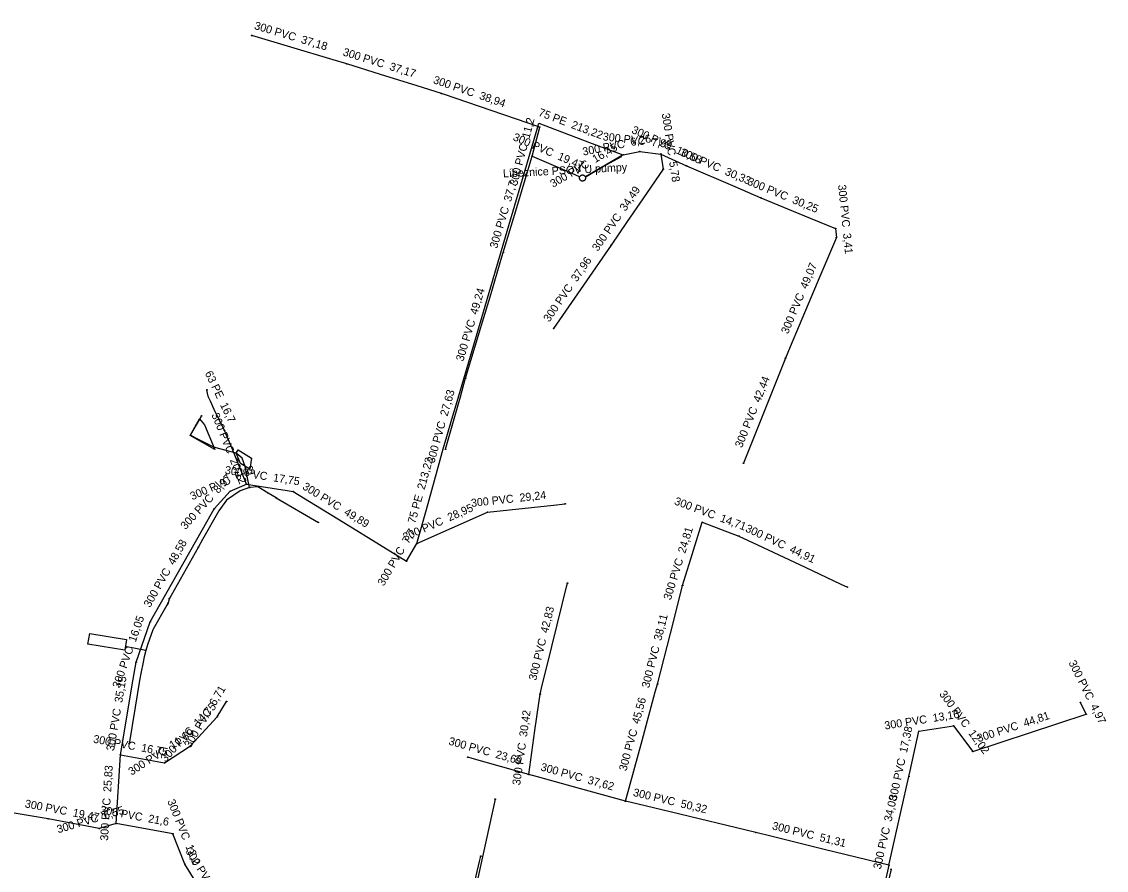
# Model space of a CAD drawing. Extents: x -736536 to -735428, y -1032997 to -1031649.
# Drawn here: x -736011.6 to -735605.1, y -1031966.8 to -1031648.8 of the extents above; entities that cross this region are included whole.
import ezdxf

# ---------------------------------------------------------------- set-up
doc = ezdxf.new("R2010")
doc.units = 0
for name, color, linetype in [('Vrstva 1', 7, 'Continuous'), ('Vrstva 20', 7, 'Continuous'), ('Vrstva 26', 7, 'Continuous'), ('Vrstva 29', 7, 'Continuous'), ('Vrstva 31', 7, 'Continuous'), ('Vrstva 63', 7, 'Continuous')]:
    doc.layers.add(name, color=color, linetype=linetype)

# ---------------------------------------------------------------- blocks, each defined once
blk = doc.blocks.new('100')
at = {"layer": 'Vrstva 1'}
blk.add_circle((0, 0), 0.127, dxfattribs=at)

msp = doc.modelspace()

# ---------------------------------------------------------------- linework, layer by layer
at = {"layer": 'Vrstva 20'}
for p, q in [((-735820.296, -1031699.16), (-735817.455, -1031688.322)), ((-735786.106, -1031698.693), (-735779.97, -1031697.473)), ((-735779.97, -1031697.473), (-735772.029, -1031698.389)), ((-735786.106, -1031698.693), (-735800.311, -1031706.996)), ((-735772.029, -1031698.389), (-735771.155, -1031704.099)), ((-735772.029, -1031698.389), (-735762.411, -1031702.801)), ((-735706.576, -1031726.287), (-735706.228, -1031729.678)), ((-735934.93, -1031803.47), (-735935.609, -1031802.05)), ((-735933.449, -1031824.778), (-735927.373, -1031822.12)), ((-735939.48, -1031831.417), (-735933.449, -1031824.778)), ((-735916.227, -1031827.217), (-735919.28, -1031825.43)), ((-735916.227, -1031827.217), (-735900.419, -1031836.451)), ((-735863.443, -1031844.339), (-735836.971, -1031832.623)), ((-735756.516, -1031836.412), (-735742.743, -1031841.571)), ((-735867.326, -1031850.993), (-735863.443, -1031844.339)), ((-735968.698, -1031888.847), (-735963.427, -1031873.69)), ((-735965.149, -1031884.46), (-735972.819, -1031882.989)), ((-735938.3, -1031909.34), (-735934.869, -1031903.569)), ((-735612.55, -1031908.34), (-735614.77, -1031903.89)), ((-735655.13, -1031922.3), (-735612.55, -1031908.34)), ((-735948.31, -1031920.17), (-735938.3, -1031909.34)), ((-735675.286, -1031914.711), (-735662.29, -1031912.64)), ((-735662.29, -1031912.64), (-735655.13, -1031922.3)), ((-735958.13, -1031926.52), (-735948.31, -1031920.17)), ((-735976.239, -1031949.279), (-735974.609, -1031923.5)), ((-735974.609, -1031923.5), (-735958.13, -1031926.52)), ((-735834.138, -1031940.181), (-735843.846, -1031984.129)), ((-735982.52, -1031951.151), (-736001.655, -1031947.538)), ((-735976.239, -1031949.279), (-735982.52, -1031951.151)), ((-735954.989, -1031953.149), (-735976.239, -1031949.279)), ((-735950.439, -1031964.47), (-735954.989, -1031953.149)), ((-735686.54, -1031964.89), (-735693.87, -1031996.69)), ((-735685.74, -1031966.45), (-735693.01, -1031998.06))]:
    msp.add_line(p, q, dxfattribs=at)
for points in [[(-735889.783, -1031664.645), (-735894.91, -1031663.114), (-735910.794, -1031658.372), (-735925.414, -1031654.008)], [(-735854.293, -1031675.69), (-735863.352, -1031672.875), (-735877.153, -1031668.578), (-735889.783, -1031664.645)], [(-735817.455, -1031688.322), (-735853.553, -1031675.944), (-735854.293, -1031675.69)], [(-735863.443, -1031844.339), (-735859.904, -1031831.549), (-735857.921, -1031824.379), (-735855.923, -1031817.158), (-735853.638, -1031808.899), (-735852.278, -1031804.273), (-735850.361, -1031797.75), (-735848.411, -1031791.117), (-735845.313, -1031780.577), (-735841.563, -1031767.821), (-735838.542, -1031757.541), (-735833.652, -1031740.908), (-735829.042, -1031725.225), (-735822.326, -1031702.377), (-735818.543, -1031689.506), (-735817.775, -1031686.893), (-735809.294, -1031690.074), (-735797.784, -1031694.392), (-735786.849, -1031698.493), (-735786.818, -1031698.949), (-735787.205, -1031699.516), (-735792.386, -1031702.509), (-735798.171, -1031705.852), (-735799.174, -1031706.431), (-735800.286, -1031707.074)], [(-735831.109, -1031735.277), (-735826.452, -1031719.721), (-735822.564, -1031706.734), (-735820.296, -1031699.16)], [(-735820.296, -1031699.16), (-735805.44, -1031705.571), (-735802.689, -1031706.759), (-735802.422, -1031706.874)], [(-735771.155, -1031704.099), (-735778.751, -1031715.131), (-735784.659, -1031723.711), (-735790.716, -1031732.506)], [(-735762.411, -1031702.801), (-735744.254, -1031710.598), (-735734.544, -1031714.767)], [(-735734.544, -1031714.767), (-735716.049, -1031722.385), (-735706.576, -1031726.287)], [(-735706.228, -1031729.678), (-735712.382, -1031744.269), (-735720.139, -1031762.658), (-735723.519, -1031770.672), (-735725.298, -1031774.89)], [(-735790.716, -1031732.506), (-735801.077, -1031747.573), (-735812.226, -1031763.786)], [(-735845.23, -1031782.445), (-735841.615, -1031770.369), (-735839.644, -1031763.785), (-735838.901, -1031761.304), (-735836.076, -1031751.867), (-735831.602, -1031736.925), (-735831.109, -1031735.277)], [(-735725.298, -1031774.89), (-735731.533, -1031790.462), (-735738.308, -1031807.383), (-735741.072, -1031814.286)], [(-735852.743, -1031809.036), (-735850.503, -1031801.107), (-735847.794, -1031791.518), (-735847.178, -1031789.338), (-735845.838, -1031784.595), (-735845.23, -1031782.445)], [(-735935.609, -1031802.05), (-735939.418, -1031794.096), (-735940.889, -1031791.024), (-735941.59, -1031789.56), (-735941.735, -1031789.104), (-735941.88, -1031788.649), (-735942.18, -1031786.779)], [(-735948.319, -1031803.8), (-735946.419, -1031800.452), (-735944.519, -1031797.105), (-735944.206, -1031796.553)], [(-735927.373, -1031822.12), (-735932.78, -1031808.776), (-735934.93, -1031803.47)], [(-735931.25, -1031810.5), (-735937.355, -1031808.818), (-735939.56, -1031808.21), (-735946.29, -1031804.821), (-735948.319, -1031803.8)], [(-735926.22, -1031823.35), (-735927.844, -1031815.494), (-735928.962, -1031812.392), (-735931.25, -1031810.5)], [(-735926.22, -1031823.35), (-735929.737, -1031824.613), (-735934.79, -1031828.132), (-735937.7, -1031832.116), (-735943.799, -1031842.904), (-735945.431, -1031845.791)], [(-735927.373, -1031822.12), (-735912.103, -1031824.51), (-735909.832, -1031824.865)], [(-735919.28, -1031825.43), (-735923.13, -1031823.09), (-735926.22, -1031823.35)], [(-735909.832, -1031824.865), (-735890.865, -1031836.53), (-735877.547, -1031844.725), (-735867.326, -1031850.993)], [(-735963.427, -1031873.69), (-735957.582, -1031863.372), (-735948.545, -1031847.419), (-735943.842, -1031839.116), (-735939.48, -1031831.417)], [(-735836.971, -1031832.623), (-735812.224, -1031829.935), (-735807.903, -1031829.466)], [(-735763.911, -1031860.098), (-735760.263, -1031848.513), (-735756.516, -1031836.412)], [(-735742.743, -1031841.571), (-735735.83, -1031844.844), (-735717.973, -1031853.263), (-735704.55, -1031859.595), (-735702.107, -1031860.686)], [(-735945.431, -1031845.791), (-735955.633, -1031863.856), (-735956.263, -1031864.971)], [(-735817.282, -1031900.798), (-735816.768, -1031898.592), (-735812.907, -1031882.975), (-735808.872, -1031866.657), (-735807.243, -1031860.067), (-735807.018, -1031859.213)], [(-735773.296, -1031897.029), (-735767.226, -1031873.214), (-735763.911, -1031860.098)], [(-735956.757, -1031866.687), (-735957.155, -1031867.424), (-735962.381, -1031876.493), (-735962.507, -1031876.718), (-735964.427, -1031882.346), (-735965.149, -1031884.46)], [(-735956.263, -1031864.971), (-735956.373, -1031865.176), (-735956.699, -1031866.579), (-735956.757, -1031866.687)], [(-735965.149, -1031884.46), (-735965.726, -1031886.865), (-735966.275, -1031889.424), (-735966.896, -1031892.397), (-735967.435, -1031895.655), (-735969.1, -1031905.714), (-735971.359, -1031919.369)], [(-735974.609, -1031923.5), (-735969.79, -1031895.246), (-735968.698, -1031888.847)], [(-735821.573, -1031930.911), (-735819.243, -1031914.411), (-735817.792, -1031904.169), (-735817.282, -1031900.798)], [(-735785.319, -1031940.973), (-735779.082, -1031918.17), (-735774.11, -1031899.924), (-735773.296, -1031897.029)], [(-735679.027, -1031931.646), (-735678.558, -1031929.492), (-735675.34, -1031914.72), (-735675.286, -1031914.711)], [(-735821.573, -1031930.911), (-735842.776, -1031924.92), (-735844.365, -1031924.466)], [(-735785.319, -1031940.973), (-735802.472, -1031936.196), (-735818.252, -1031931.832), (-735821.573, -1031930.911)], [(-735686.54, -1031964.89), (-735686.184, -1031963.313), (-735681.905, -1031944.382), (-735679.03, -1031931.66), (-735679.027, -1031931.646)], [(-736001.655, -1031947.538), (-736020.574, -1031944.355), (-736026.457, -1031943.366), (-736039.331, -1031941.2), (-736047.575, -1031939.813)], [(-735736.376, -1031952.663), (-735768.585, -1031944.958), (-735780.541, -1031942.091), (-735785.319, -1031940.973)], [(-735686.54, -1031964.89), (-735710.762, -1031958.968), (-735730.309, -1031954.179), (-735736.376, -1031952.663)], [(-735851.498, -1032013.031), (-735848.58, -1032000.434), (-735846.456, -1031991.334), (-735844.114, -1031981.299), (-735839.958, -1031963.488), (-735839.492, -1031961.535)], [(-735932.31, -1031993.89), (-735944.301, -1031974.43), (-735950.439, -1031964.47)]]:
    msp.add_lwpolyline(points, dxfattribs=at)
at = {"layer": 'Vrstva 26'}
msp.add_lwpolyline([(-735802.492, -1031707.702), (-735802.515, -1031707.619), (-735802.53, -1031707.522), (-735802.538, -1031707.41), (-735802.533, -1031707.26), (-735802.508, -1031707.141), (-735802.484, -1031707.026), (-735802.422, -1031706.874), (-735802.386, -1031706.807), (-735802.321, -1031706.706), (-735802.263, -1031706.635), (-735802.16, -1031706.528), (-735802.067, -1031706.452), (-735801.912, -1031706.359), (-735801.776, -1031706.3), (-735801.689, -1031706.274), (-735801.596, -1031706.253), (-735801.512, -1031706.239), (-735801.459, -1031706.236), (-735801.392, -1031706.233), (-735801.288, -1031706.238), (-735801.213, -1031706.249), (-735801.154, -1031706.258), (-735801.096, -1031706.274), (-735801.038, -1031706.289), (-735800.926, -1031706.332), (-735800.819, -1031706.387), (-735800.741, -1031706.437), (-735800.671, -1031706.49), (-735800.604, -1031706.548), (-735800.486, -1031706.679), (-735800.417, -1031706.779), (-735800.358, -1031706.887), (-735800.326, -1031706.959), (-735800.286, -1031707.074), (-735800.25, -1031707.282), (-735800.245, -1031707.38), (-735800.251, -1031707.5), (-735800.261, -1031707.56), (-735800.301, -1031707.735), (-735800.358, -1031707.874), (-735800.396, -1031707.949), (-735800.464, -1031708.055), (-735800.558, -1031708.166), (-735800.671, -1031708.271), (-735800.786, -1031708.353), (-735800.872, -1031708.401), (-735800.93, -1031708.43), (-735801.038, -1031708.472), (-735801.154, -1031708.503), (-735801.272, -1031708.522), (-735801.363, -1031708.526), (-735801.502, -1031708.522), (-735801.596, -1031708.508), (-735801.747, -1031708.472), (-735801.843, -1031708.435), (-735801.97, -1031708.371), (-735802.081, -1031708.297), (-735802.16, -1031708.233), (-735802.21, -1031708.184), (-735802.251, -1031708.14), (-735802.313, -1031708.064), (-735802.364, -1031707.988), (-735802.408, -1031707.911), (-735802.44, -1031707.847), (-735802.457, -1031707.804), (-735802.466, -1031707.781), (-735802.478, -1031707.749), (-735802.492, -1031707.702)], dxfattribs=at)
at = {"layer": 'Vrstva 31'}
for points in [[(-735939.182, -1031809.087), (-735948.514, -1031803.821), (-735944.921, -1031797.648), (-735943.1, -1031799.849), (-735939.182, -1031809.087)], [(-735930.517, -1031809.294), (-735925.423, -1031812.399), (-735926.105, -1031816.554), (-735929.583, -1031814.435), (-735931.25, -1031810.5), (-735930.517, -1031809.294)], [(-735986.123, -1031878.072), (-735972.316, -1031880.387), (-735972.977, -1031884.332), (-735986.785, -1031882.017), (-735986.123, -1031878.072)]]:
    msp.add_lwpolyline(points, dxfattribs=at)

# ---------------------------------------------------------------- block references
at = {"layer": 'Vrstva 29'}
for p, xscale, yscale, rotation in [((-735925.414, -1031654.008), 1.035124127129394, 1.0351241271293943, 157.49634583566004), ((-735889.783, -1031664.645), 1.0335064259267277, 1.033506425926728, -23.04128150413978), ((-735854.293, -1031675.69), 1.0316957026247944, 1.0316957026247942, -23.584588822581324), ((-735817.455, -1031688.322), 0.9999999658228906, 0.9999999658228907, 117.99999982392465), ((-735779.97, -1031697.473), 0.9999999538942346, 0.9999999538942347, 2.0000000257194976), ((-735820.296, -1031699.16), 1.0169561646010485, 1.0169561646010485, 26.97601647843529), ((-735786.106, -1031698.693), 1.0275072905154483, 1.027507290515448, 24.689105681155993), ((-735772.029, -1031698.389), 1.035124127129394, 1.0351241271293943, -22.503654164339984), ((-735771.155, -1031704.099), 0.9999999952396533, 0.9999999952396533, 77.00000056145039), ((-735762.411, -1031702.801), 1.0169561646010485, 1.0169561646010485, -26.97601647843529), ((-735734.544, -1031714.767), 1.0198568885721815, 1.0198568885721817, -26.39398240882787), ((-735706.576, -1031726.287), 0.9999999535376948, 0.9999999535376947, -53.99999865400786), ((-735706.228, -1031729.678), 0.9999999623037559, 0.999999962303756, 80.99999986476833), ((-735790.716, -1031732.506), 0.9999999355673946, 0.9999999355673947, 55.0000006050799), ((-735831.109, -1031735.277), 0.9999999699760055, 0.9999999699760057, 73.00000033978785), ((-735812.226, -1031763.786), 0.9999999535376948, 0.9999999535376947, -126.00000134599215), ((-735725.298, -1031774.89), 0.9999999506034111, 0.9999999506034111, 67.99999971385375), ((-735845.23, -1031782.445), 0.9999999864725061, 0.9999999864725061, 74.0000013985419), ((-735942.18, -1031786.779), 0.9999999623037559, 0.999999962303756, 99.00000013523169), ((-735944.206, -1031796.553), 0.9999999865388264, 0.9999999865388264, 59.99999955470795), ((-735935.609, -1031802.05), 0.9999999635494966, 0.9999999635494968, -65.00000039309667), ((-735934.93, -1031803.47), 0.9999999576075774, 0.9999999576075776, -66.99999911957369), ((-735948.319, -1031803.8), 0.9999999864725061, 0.9999999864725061, -74.0000013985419), ((-735931.25, -1031810.5), 1.0072562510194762, 1.0072562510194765, -28.766663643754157), ((-735852.743, -1031809.036), 0.9999999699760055, 0.9999999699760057, -106.99999966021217), ((-735741.072, -1031814.286), 0.9999999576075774, 0.9999999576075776, -113.00000088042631), ((-735927.373, -1031822.12), 0.9999999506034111, 0.9999999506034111, 67.99999971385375), ((-735926.22, -1031823.35), 1.0045862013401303, 1.00458620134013, 13.17409066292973), ((-735933.449, -1031824.778), 0.9999999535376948, 0.9999999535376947, 36.000001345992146), ((-735919.28, -1031825.43), 0.9999999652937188, 0.9999999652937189, -31.9999973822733), ((-735916.227, -1031827.217), 0.9999999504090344, 0.9999999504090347, -31.000001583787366), ((-735909.832, -1031824.865), 1.0275072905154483, 1.027507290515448, -24.689105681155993), ((-735939.48, -1031831.417), 0.9999999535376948, 0.9999999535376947, 53.99999865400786), ((-735807.903, -1031829.466), 1.0011216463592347, 1.0011216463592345, 6.5826102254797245), ((-735836.971, -1031832.623), 0.999999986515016, 0.9999999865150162, 15.000000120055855), ((-735900.419, -1031836.451), 0.9999999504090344, 0.9999999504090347, -31.000001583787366), ((-735756.516, -1031836.412), 1.0138864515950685, 1.0138864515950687, 27.5653151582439), ((-735742.743, -1031841.571), 1.0198568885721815, 1.0198568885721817, -26.39398240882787), ((-735945.431, -1031845.791), 0.999999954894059, 0.9999999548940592, 60.999999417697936), ((-735863.443, -1031844.339), 0.9999999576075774, 0.9999999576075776, 66.99999911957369), ((-735867.326, -1031850.993), 1.0028916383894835, 1.0028916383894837, -166.30279209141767), ((-735807.018, -1031859.213), 0.999999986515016, 0.9999999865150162, 74.99999987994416), ((-735763.911, -1031860.098), 0.9999999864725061, 0.9999999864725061, 74.0000013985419), ((-735702.107, -1031860.686), 1.0169561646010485, 1.0169561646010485, -26.97601647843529), ((-735956.263, -1031864.971), 0.999999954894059, 0.9999999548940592, 60.999999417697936), ((-735963.427, -1031873.69), 0.9999999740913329, 0.9999999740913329, 65.99999939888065), ((-735965.149, -1031884.46), 0.9999999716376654, 0.9999999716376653, 29.999998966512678), ((-735968.698, -1031888.847), 0.9999999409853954, 0.9999999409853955, 75.99999967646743), ((-735773.296, -1031897.029), 0.999999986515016, 0.9999999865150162, 74.99999987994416), ((-735817.282, -1031900.798), 0.9999999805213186, 0.9999999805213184, 79.00000058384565), ((-735934.869, -1031903.569), 0.9999999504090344, 0.9999999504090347, 58.99999841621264), ((-735614.77, -1031903.89), 0.999999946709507, 0.999999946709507, 117.00000088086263), ((-735938.3, -1031909.34), 0.9999999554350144, 0.9999999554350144, 53.00000079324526), ((-735612.55, -1031908.34), 0.9999999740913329, 0.9999999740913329, -114.00000060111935), ((-735662.29, -1031912.64), 1.025136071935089, 1.0251360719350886, 154.74924162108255), ((-735675.286, -1031914.711), 1.00837761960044, 1.00837761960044, 11.626378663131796), ((-735971.359, -1031919.369), 0.9999999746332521, 0.9999999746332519, -99.99999944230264), ((-735948.31, -1031920.17), 0.9999999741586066, 0.9999999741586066, 39.999998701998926), ((-735974.609, -1031923.5), 1.000191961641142, 1.000191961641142, 82.91099886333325), ((-735844.365, -1031924.466), 1.0365458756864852, 1.0365458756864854, 158.02850914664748), ((-735655.13, -1031922.3), 1.0335064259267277, 1.033506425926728, 156.95871849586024), ((-735958.13, -1031926.52), 1.0060666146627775, 1.0060666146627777, 12.654735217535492), ((-735821.573, -1031930.911), 1.035124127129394, 1.0351241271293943, -22.503654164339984), ((-735679.027, -1031931.646), 0.999999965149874, 0.9999999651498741, 77.9999999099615), ((-735834.138, -1031940.181), 0.9999999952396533, 0.9999999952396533, -102.9999994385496), ((-735785.319, -1031940.973), 0.999999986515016, 0.9999999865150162, -15.000000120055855), ((-736001.655, -1031947.538), 1.0060666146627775, 1.0060666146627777, -12.654735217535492), ((-735976.239, -1031949.279), 1.0002788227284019, 1.0002788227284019, 3.2906995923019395), ((-735982.52, -1031951.151), 1.0002788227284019, 1.0002788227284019, 3.2906995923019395), ((-735954.989, -1031953.149), 0.9999999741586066, 0.9999999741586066, -39.999998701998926), ((-735736.376, -1031952.663), 0.999999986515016, 0.9999999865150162, -15.000000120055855), ((-735839.492, -1031961.535), 0.9999999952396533, 0.9999999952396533, 77.00000056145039), ((-735950.439, -1031964.47), 0.9999999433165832, 0.999999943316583, -64.0000000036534), ((-735686.54, -1031964.89), 0.9999999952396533, 0.9999999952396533, 77.00000056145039), ((-735685.74, -1031966.45), 0.9999999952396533, 0.9999999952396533, 77.00000056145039)]:
    msp.add_blockref('100', p, dxfattribs=dict(at, xscale=xscale, yscale=yscale, rotation=rotation))
msp.add_blockref('100', (-735956.757, -1031866.687), dxfattribs=at)

# ---------------------------------------------------------------- texts
at = {"layer": 'Vrstva 63'}
for s, rotation, p in [('300 PVC  37,18', 343.38, (-735924.664, -1031651.519)), ('300 PVC  37,17', 342.7, (-735891.467, -1031661.395)), ('300 PVC  38,94', 341.07, (-735857.628, -1031671.797)), ('75 PE  213,22', 339.44, (-735818.199, -1031683.956)), ('300 PVC  11,2', 75.31, (-735825.947, -1031710.464)), ('300 PVC  5,78', 278.7, (-735771.707, -1031683.302)), ('300 PVC  10,58', 335.36, (-735783.267, -1031690.373)), ('300 PVC  19,47', 336.66, (-735827.753, -1031693.111)), ('300 PVC  6,26', 11.25, (-735801.098, -1031699.024)), ('300 PVC  7,99', 353.42, (-735793.918, -1031693.246)), ('300 PVC  16,45', 30.31, (-735812.42, -1031711.063)), ('300 PVC  30,33', 336.76, (-735765.099, -1031698.816)), ('Líbeznice PSOV U pumpy', 3, (-735831.149, -1031707.191)), ('300 PVC  37,7', 73.33, (-735833.442, -1031734)), ('300 PVC  30,25', 337.61, (-735739.905, -1031709.746)), ('300 PVC  3,41', 275.86, (-735705.633, -1031710.002)), ('300 PVC  34,49', 55.45, (-735795.655, -1031735.095)), ('300 PVC  37,96', 55.49, (-735813.872, -1031761.594)), ('300 PVC  49,07', 67.13, (-735724.392, -1031766.053)), ('300 PVC  49,24', 73.33, (-735846.106, -1031776.302)), ('63 PE  16,7', 295.59, (-735943.045, -1031780.5)), ('300 PVC  42,44', 68.18, (-735741.646, -1031808.728)), ('300 PVC  27,63', 74.22, (-735856.975, -1031814.448)), ('300 PVC  20,12', 292.06, (-735940.545, -1031796.119)), ('300 PVC  6,63', 23.63, (-735947.708, -1031828.178)), ('300 PVC  17,75', 351.11, (-735935.61, -1031818.2)), ('75 PE  213,22', 74.54, (-735864.126, -1031837.066)), ('300 PVC  8,97', 47.75, (-735950.208, -1031839.36)), ('300 PVC  49,89', 328.41, (-735906.655, -1031823.767)), ('300 PVC  29,24', 6.2, (-735843.05, -1031830.668)), ('300 PVC  14,71', 339.46, (-735767.23, -1031829.619)), ('300 PVC  28,95', 23.87, (-735867.964, -1031843.495)), ('300 PVC  7,7', 59.73, (-735875.898, -1031860.521)), ('300 PVC  24,81', 72.8, (-735768.32, -1031865.751)), ('300 PVC  44,91', 334.76, (-735740.61, -1031839.717)), ('300 PVC  48,58', 60.47, (-735963.517, -1031868.575)), ('300 PVC  42,83', 76.11, (-735818.773, -1031895.869)), ('300 PVC  16,05', 70.82, (-735974.913, -1031898.799)), ('300 PVC  38,11', 75.7, (-735776.407, -1031898.707)), ('300 PVC  4,97', 296.51, (-735619.296, -1031888.99)), ('300 PVC  35,15', 80.32, (-735977.032, -1031922.243)), ('300 PVC  6,71', 59.27, (-735948.358, -1031921.173)), ('300 PVC  12,02', 306.55, (-735667.832, -1031900.798)), ('300 PVC  14,75', 47.25, (-735957.695, -1031926.492)), ('300 PVC  45,56', 74.76, (-735784.953, -1031929.829)), ('300 PVC  30,42', 81.96, (-735824.787, -1031935.074)), ('300 PVC  13,16', 9.06, (-735687.966, -1031914.1)), ('300 PVC  44,81', 18.15, (-735652.958, -1031918.851)), ('300 PVC  17,38', 77.71, (-735683.697, -1031940.869)), ('300 PVC  16,75', 349.62, (-735984.998, -1031918.954)), ('300 PVC  11,69', 32.89, (-735970.442, -1031931.386)), ('300 PVC  23,69', 344.22, (-735851.831, -1031919.658)), ('300 PVC  25,83', 86.38, (-735979.258, -1031955.817)), ('300 PVC  37,62', 344.44, (-735817.324, -1031929.361)), ('300 PVC  50,32', 346.55, (-735782.638, -1031938.924)), ('300 PVC  19,47', 349.31, (-736010.629, -1031943.198)), ('300 PVC  12,2', 291.9, (-735957.118, -1031940.882)), ('300 PVC  34,08', 77.27, (-735689.593, -1031966.617)), ('300 PVC  6,55', 16.6, (-735997.943, -1031952.983)), ('300 PVC  21,6', 349.68, (-735982.367, -1031945.52)), ('300 PVC  51,31', 346.23, (-735730.523, -1031951.448)), ('300 PVC  34,56', 301.64, (-735950.334, -1031959.681))]:
    msp.add_text(s, height=2.99999, rotation=rotation, dxfattribs=at).set_placement(p)

doc.saveas('drawing.dxf')
